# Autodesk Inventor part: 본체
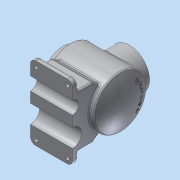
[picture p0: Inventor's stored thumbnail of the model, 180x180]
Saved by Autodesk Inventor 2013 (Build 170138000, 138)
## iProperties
Created: 2018-08
Part Number: 본체
Material: 알루미늄 6061
Document SubType Name: Modeling
Designer: dgall
Density: 1 g/cm^3
Author: dgall
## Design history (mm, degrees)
sketch "스케치1"
  geometry: L1 (0, 0)-(120, 0); L2 (0, 0)-(0, 38); L3 (0, 38)-(12, 38); L4 (12, 38)-(12, 50); L5 (12, 50)-(108.671, 50); A1 r 116 centre (4, 0) between (120, 0) and (108.671, 50)
  constraints: 11 end point, 2 parallel, 2 perpendicular, 2 point on circle, 1 centre point, 1 horizontal, 1 horizontal alignment
  dimensions: "d0" = 120 distance of L1.start L1.end; "d1" = 116 radius of A1; "d2" = 76 diameter of L3 L1; "d3" = 100 diameter of L5 L1; "d4" = 108 distance from line of L1.end L4
revolve "회전1" sketch "스케치1" stored, may be unused: angle "d5" = 90 deg
node "작업 평면1"
sketch "스케치2"
  geometry: L1 (-12, 50)-(-12, -50) reference; C1 r 38 at (-62, 0); 1 further point
  constraints: 1 centre point, 1 horizontal alignment
  dimensions: "d7" = 76 diameter of C1; "d9" = 50 distance from line of L1 C1.centre
extrude "돌출1" join sketch "스케치2" stored distance "d10" = 10; taper "d11" = 0 deg
node "작업 평면2"
sketch "스케치3"
  geometry: L1 (-40.304, -29.59)-(-50, -43.437); L2 (-50, -43.437)-(-50, -72); L3 (-50, -72)-(-70, -72); L4 (-70, -72)-(-70, -82); L5 (-70, -82)-(70, -82); L6 (70, -82)-(70, -72); L7 (70, -72)-(50, -72); L8 (50, -72)-(50, -43.437); L9 (50, -43.437)-(40.304, -29.59); L10 (-50, -43.437)-(-70, -72); A1 r 50 centre (0, 0) between (-40.304, -29.59) and (40.304, -29.59) reference; 2 further points
  constraints: 20 end point, 6 perpendicular, 3 horizontal alignment, 2 point on circle, 1 collinear, 1 midpoint, 1 vertical, 1 vertical alignment
  dimensions: "d13" = 10 distance of L5.end L6.end; "d15" = 82 distance from line of L5 point (0, 0); "d16" = 20 distance between parallel lines of L2 L4; "d17" = 20 distance between parallel lines of L6 L8; "d19" = 140 distance between parallel lines of L6 L4; "d20" = 35 deg angle of L1 L4
extrude "돌출2" join sketch "스케치3" distance "d21" = 80; taper "d22" = 0 deg
sketch "스케치4"
  geometry: L1 (-70, -82)-(70, -82) reference; A1 r 50 centre (0, 0) between (-40.304, -29.59) and (40.304, -29.59) reference; A2 r 17.5 centre (-22.5, -82) between (-5, -82) and (-40, -82); A3 r 12.5 centre (27.5, -82) between (40, -82) and (15, -82)
  constraints: 6 point on line, 4 point on circle, 2 centre point
  dimensions: "d24" = 12.5 radius of A3; "d26" = 17.5 radius of A2; "d27" = 22.5 horizontal distance of A1.centre A2.centre; "d28" = 27.5 horizontal distance of A3.centre A1.centre
extrude "돌출3" cut sketch "스케치4" stored distance "d29" = 80; taper "d30" = 0 deg
sketch "스케치5"
  geometry: L1 (0, -38)-(0, 38) reference; L2 (0, 38)-(12, 38) reference; L3 (12, 38)-(12, 50) reference; L4 (12, 50)-(24, 50) reference; L5 (24, 50)-(24, 65) reference; L6 (24, 65)-(100, 65) reference; L7 (100, 65)-(100, 50) reference; L8 (100, 50)-(108.671, 50) reference; L9 (108.671, -50)-(100, -50) reference; L10 (100, -50)-(100, -82) reference; L11 (100, -82)-(20, -82) reference; L12 (20, -82)-(20, -50) reference; L13 (20, -50)-(12, -50) reference; L14 (12, -50)-(12, -38) reference; L15 (12, -38)-(0, -38) reference; L16 (0, 0)-(120, 0); L17 (102.163, 40)-(22, 40); L18 (22, 27)-(0, 27); L19 (22, 27)-(22, 40); L20 (0, 27)-(0, 0); A1 r 116 centre (4, 0) between (108.671, -50) and (108.671, 50) reference; A2 r 106 centre (4, 0) between (110, 0) and (102.163, 40)
  constraints: 10 end point, 3 point on circle, 2 point on line, 1 centre point, 1 collinear, 1 perpendicular
  dimensions: "d31" = 54 diameter of L18 L16; "d33" = 22 distance between parallel lines of L19 L1; "d34" = 10 radial gap between concentric circles of A1 A2; "d35" = 80 diameter of L17 L16
revolve "회전2" sketch "스케치5" stored, may be unused: angle "d36" = 90 deg
sketch "스케치6"
  geometry: C1 r 38 at (0, 0) reference; C2 r 27 at (0, 0); 1 further point
  constraints: 1 centre point, 1 coincident
  dimensions: "d37" = 54 diameter of C2
extrude "돌출4" cut sketch "스케치6" stored distance "d38" = 80; taper "d39" = 0 deg
fillet "모깎기1" dims "d40" = 10
fillet "모깎기2" dims "d41" = 3
fillet "모깎기3" dims "d42" = 3
fillet "모깎기4" dims "d43" = 3
fillet "모깎기5" dims "d44" = 3
fillet "모깎기6" dims "d45" = 3
fillet "모깎기7" dims "d46" = 3
sketch "스케치7"
  geometry: L1 (80, 100)-(80, 80) reference; L2 (80, 80)-(0, 80) reference; L3 (0, 80)-(0, 100) reference; L4 (10, 110)-(70, 110) reference; L5 (80, 55)-(80, 35) reference; L6 (80, 35)-(0, 35) reference; L7 (0, 35)-(0, 55) reference; L8 (0, 55)-(80, 55) reference; L9 (80, 0)-(80, -20) reference; L10 (70, -30)-(10, -30) reference; L11 (0, -20)-(0, 0) reference; L12 (0, 0)-(80, 0) reference; C1 r 4 at (10, -20); C2 r 4 at (70, -20); C3 r 4 at (10, 100); C4 r 4 at (70, 100); A1 r 10 centre (70, -20) between (70, -30) and (80, -20) reference; A2 r 10 centre (10, -20) between (0, -20) and (10, -30) reference; A3 r 10 centre (10, 100) between (10, 110) and (0, 100) reference; A4 r 10 centre (70, 100) between (80, 100) and (70, 110) reference; A5 r 10 centre (70, -20) between (70, -30) and (80, -20) reference; A6 r 10 centre (10, -20) between (0, -20) and (10, -30) reference; 1 further point
  constraints: 4 centre point, 4 coincident
  dimensions: "d47" = 8 diameter of C1; "d48" = 8 diameter of C2; "d49" = 8 diameter of C3; "d50" = 8 diameter of C4
extrude "돌출5" cut sketch "스케치7" distance "d51" = 10; taper "d52" = 0 deg
fillet "모깎기8" dims "d53" = 3
fillet "모깎기9" dims "d54" = 3
sketch "스케치8"
  geometry: C1 r 27 at (0, 0) reference; 1 further point
  constraints: 1 vertical alignment
  dimensions: "d55" = 32.5 distance of C1.centre point (0, 32.5)
hole "구멍1" sketch "스케치8" at (0, 32.5) diameter "d56" = 3.242; stored, may be unused: countersink angle "d60" = 90 deg, drill point angle "d62" = 118 deg; dims "d57" = 8, "d58" = 4, "d59" = 2, "d61" = 10
sketch "스케치9"
  geometry: C1 r 27 at (0, 0) reference; 2 further points
  constraints: 1 vertical alignment
  dimensions: "d66" = 32.5 distance of C1.centre point (0, 32.5)
hole "구멍2" sketch "스케치9" at (0, 32.5) diameter "d67" = 3.242; stored, may be unused: countersink angle "d71" = 90 deg, drill point angle "d73" = 118 deg; dims "d68" = 8, "d69" = 4, "d70" = 2, "d72" = 10
chamfer "모따기1" distance "d77" = 1; stored, may be unused: second distance "d78" = 2, angle "d79" = 45 deg
node "작업 평면3"
sketch "스케치10"
  geometry: C1 r 32.5 at (0, 0); 1 further point
  constraints: 1 centre point, 1 coincident, 1 other
  dimensions: "d80" = 65 diameter of C1
feature "엠보싱1" sketch "스케치10" dims "d13" = 10, "d15" = 82, "d16" = 20, "d17" = 20, "d19" = 140, "d20" = 35 deg, "d81" = 0.5, "d82" = 0
node "솔리드1"
pattern_circular "원형 패턴1" dims angle "d64" = 360 deg
pattern_circular "원형 패턴2" dims angle "d75" = 360 deg
node "절단 모서리 투영1"
node "절단 모서리 투영2"
node "절단 모서리 투영3"
other parameters: "d6" = 65, "d12" = -8
